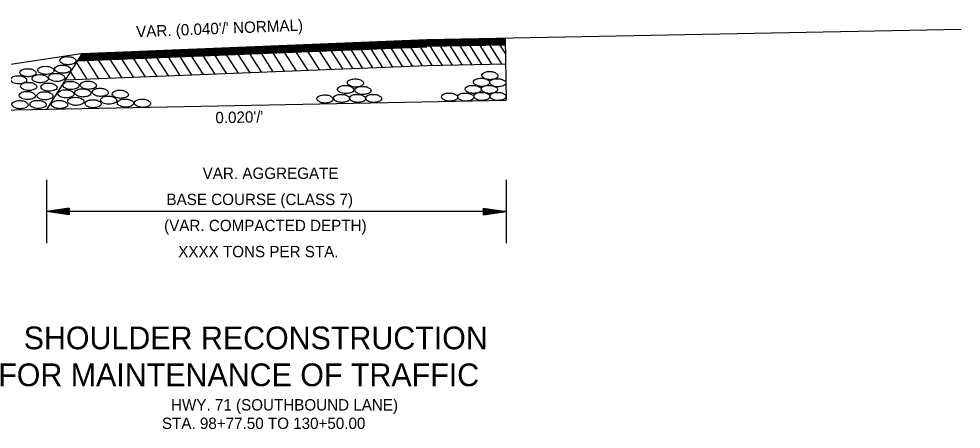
# Model space of a CAD drawing. Extents: x 635488 to 635865, y 290537 to 290973.
# Drawn here: x 635514.88 to 635564.67, y 290872.13 to 290893.8 of the extents above; entities that cross this region are included whole.
import ezdxf

# ---------------------------------------------------------------- set-up
doc = ezdxf.new("R2010")
doc.units = 0
doc.layers.add('Default', color=7, linetype='Continuous')

msp = doc.modelspace()

# ---------------------------------------------------------------- linework, layer by layer
at = {"layer": 'Default'}
for p, q in [((635564.67, 290893.24), (635536.434, 290892.685)), ((635536.434, 290892.3), (635517.962, 290891.558)), ((635536.434, 290892.333), (635517.979, 290891.586)), ((635536.434, 290892.37), (635518.005, 290891.63)), ((635536.434, 290892.412), (635518.029, 290891.67)), ((635536.434, 290892.45), (635518.061, 290891.714)), ((635536.434, 290892.488), (635518.083, 290891.748)), ((635536.434, 290892.524), (635518.111, 290891.792)), ((635536.434, 290892.566), (635518.133, 290891.832)), ((635536.434, 290892.608), (635518.164, 290891.878)), ((635536.434, 290892.641), (635518.183, 290891.907)), ((635536.434, 290892.685), (635518.211, 290891.952)), ((635540.583, 290892.724), (635536.434, 290892.641)), ((635540.584, 290892.691), (635536.434, 290892.608)), ((635540.584, 290892.65), (635536.434, 290892.566)), ((635540.585, 290892.609), (635536.434, 290892.524)), ((635540.586, 290892.572), (635536.434, 290892.488)), ((635540.586, 290892.533), (635536.434, 290892.45)), ((635540.587, 290892.495), (635536.434, 290892.412)), ((635540.587, 290892.452), (635536.434, 290892.37)), ((635540.588, 290892.415), (635536.434, 290892.333)), ((635537.267, 290891.333), (635536.632, 290892.337)), ((635537.793, 290891.343), (635537.158, 290892.347)), ((635538.318, 290891.353), (635537.684, 290892.357)), ((635538.844, 290891.364), (635538.21, 290892.368)), ((635539.37, 290891.374), (635538.735, 290892.378)), ((635539.896, 290891.385), (635539.261, 290892.388)), ((635540.421, 290891.395), (635539.787, 290892.399)), ((635540.595, 290891.962), (635540.313, 290892.409)), ((635540.583, 290892.735), (635540.634, 290889.503)), ((635518.177, 290891.946), (635487.759, 290887.399)), ((635518.211, 290891.952), (635516.341, 290889.006)), ((635524.648, 290890.851), (635524.03, 290891.801)), ((635525.257, 290890.875), (635524.644, 290891.826)), ((635525.873, 290890.899), (635525.261, 290891.854)), ((635526.485, 290890.923), (635525.87, 290891.879)), ((635527.106, 290890.947), (635526.487, 290891.901)), ((635527.714, 290890.972), (635527.101, 290891.924)), ((635528.329, 290890.996), (635527.715, 290891.951)), ((635528.945, 290891.02), (635528.331, 290891.974)), ((635529.555, 290891.044), (635528.94, 290892.001)), ((635530.174, 290891.069), (635529.557, 290892.026)), ((635530.788, 290891.094), (635530.168, 290892.049)), ((635531.403, 290891.117), (635530.786, 290892.072)), ((635532.019, 290891.142), (635531.4, 290892.097)), ((635532.541, 290891.162), (635531.935, 290892.122)), ((635533.065, 290891.183), (635532.462, 290892.141)), ((635533.595, 290891.204), (635532.988, 290892.164)), ((635534.123, 290891.225), (635533.513, 290892.181)), ((635534.65, 290891.246), (635534.041, 290892.207)), ((635535.175, 290891.267), (635534.567, 290892.227)), ((635535.699, 290891.287), (635535.091, 290892.249)), ((635536.215, 290891.312), (635535.612, 290892.267)), ((635536.741, 290891.322), (635536.131, 290892.288)), ((635536.454, 290891.317), (635517.329, 290890.562)), ((635518.499, 290890.608), (635517.926, 290891.502)), ((635519.117, 290890.632), (635518.504, 290891.582)), ((635519.732, 290890.657), (635519.119, 290891.606)), ((635520.345, 290890.681), (635519.733, 290891.63)), ((635520.957, 290890.706), (635520.346, 290891.655)), ((635521.574, 290890.729), (635520.964, 290891.678)), ((635522.186, 290890.754), (635521.578, 290891.705)), ((635522.805, 290890.778), (635522.192, 290891.73)), ((635523.414, 290890.802), (635522.805, 290891.751)), ((635524.032, 290890.826), (635523.419, 290891.778)), ((635540.604, 290891.398), (635536.454, 290891.317)), ((635517.887, 290890.584), (635517.611, 290891.011)), ((635540.634, 290889.491), (635495.751, 290888.594)), ((635516.341, 290885.291), (635516.341, 290881.955)), ((635540.634, 290885.291), (635540.634, 290881.955)), ((635517.541, 290883.803), (635516.341, 290883.623)), ((635540.634, 290883.623), (635516.341, 290883.623)), ((635517.541, 290883.443), (635516.341, 290883.623)), ((635517.541, 290883.773), (635516.541, 290883.623)), ((635517.541, 290883.473), (635516.541, 290883.623)), ((635517.541, 290883.742), (635516.748, 290883.623)), ((635517.541, 290883.504), (635516.748, 290883.623)), ((635517.541, 290883.712), (635516.948, 290883.623)), ((635517.541, 290883.534), (635516.948, 290883.623)), ((635517.541, 290883.681), (635517.151, 290883.623)), ((635517.541, 290883.564), (635517.151, 290883.623)), ((635517.541, 290883.651), (635517.351, 290883.623)), ((635517.541, 290883.595), (635517.351, 290883.623)), ((635517.541, 290883.803), (635517.541, 290883.443)), ((635539.434, 290883.803), (635540.634, 290883.623)), ((635539.434, 290883.443), (635539.434, 290883.803)), ((635539.434, 290883.773), (635540.434, 290883.623)), ((635539.434, 290883.742), (635540.227, 290883.623)), ((635539.434, 290883.712), (635540.027, 290883.623)), ((635539.434, 290883.682), (635539.824, 290883.623)), ((635539.434, 290883.651), (635539.624, 290883.623)), ((635539.434, 290883.443), (635540.634, 290883.623)), ((635539.434, 290883.565), (635539.824, 290883.623)), ((635539.434, 290883.504), (635540.227, 290883.623)), ((635539.434, 290883.473), (635540.434, 290883.623)), ((635539.434, 290883.534), (635540.027, 290883.623)), ((635539.434, 290883.595), (635539.624, 290883.623))]:
    msp.add_line(p, q, dxfattribs=at)
for points in [[(635517.485, 290891.798), (635517.335, 290891.797), (635517.153, 290891.733), (635517.061, 290891.649), (635517.048, 290891.596), (635517.097, 290891.504), (635517.151, 290891.462), (635517.246, 290891.412), (635517.398, 290891.381), (635517.471, 290891.37), (635517.585, 290891.382), (635517.706, 290891.402), (635517.8, 290891.441), (635517.89, 290891.51), (635517.906, 290891.571), (635517.877, 290891.652), (635517.809, 290891.708), (635517.743, 290891.75), (635517.645, 290891.781), (635517.583, 290891.797), (635517.485, 290891.798)], [(635517.209, 290891.351), (635517.058, 290891.349), (635516.877, 290891.287), (635516.787, 290891.2), (635516.771, 290891.15), (635516.819, 290891.056), (635516.872, 290891.014), (635516.971, 290890.969), (635517.119, 290890.93), (635517.195, 290890.924), (635517.307, 290890.932), (635517.43, 290890.954), (635517.525, 290890.992), (635517.613, 290891.063), (635517.628, 290891.123), (635517.602, 290891.203), (635517.533, 290891.261), (635517.469, 290891.304), (635517.366, 290891.335), (635517.304, 290891.349), (635517.209, 290891.351)], [(635515.373, 290891.162), (635515.222, 290891.161), (635515.038, 290891.1), (635514.949, 290891.013), (635514.935, 290890.964), (635514.984, 290890.868), (635515.037, 290890.827), (635515.136, 290890.782), (635515.284, 290890.745), (635515.358, 290890.738), (635515.471, 290890.746), (635515.595, 290890.767), (635515.688, 290890.805), (635515.78, 290890.877), (635515.791, 290890.935), (635515.764, 290891.016), (635515.697, 290891.072), (635515.632, 290891.116), (635515.532, 290891.148), (635515.468, 290891.161), (635515.373, 290891.162)], [(635516.017, 290890.849), (635515.869, 290890.848), (635515.685, 290890.785), (635515.598, 290890.698), (635515.582, 290890.648), (635515.629, 290890.555), (635515.683, 290890.514), (635515.782, 290890.466), (635515.928, 290890.428), (635516.006, 290890.424), (635516.115, 290890.43), (635516.24, 290890.45), (635516.335, 290890.491), (635516.424, 290890.561), (635516.438, 290890.62), (635516.41, 290890.703), (635516.341, 290890.759), (635516.28, 290890.802), (635516.177, 290890.832), (635516.113, 290890.848), (635516.017, 290890.849)], [(635516.319, 290891.289), (635516.168, 290891.287), (635515.987, 290891.225), (635515.895, 290891.137), (635515.884, 290891.089), (635515.93, 290890.994), (635515.983, 290890.954), (635516.081, 290890.905), (635516.23, 290890.868), (635516.305, 290890.862), (635516.417, 290890.873), (635516.54, 290890.893), (635516.637, 290890.93), (635516.724, 290891.003), (635516.74, 290891.061), (635516.713, 290891.142), (635516.643, 290891.198), (635516.579, 290891.24), (635516.477, 290891.273), (635516.416, 290891.287), (635516.319, 290891.289)], [(635516.888, 290890.913), (635516.74, 290890.911), (635516.556, 290890.852), (635516.469, 290890.765), (635516.453, 290890.715), (635516.5, 290890.62), (635516.554, 290890.58), (635516.653, 290890.533), (635516.799, 290890.495), (635516.877, 290890.489), (635516.988, 290890.497), (635517.111, 290890.517), (635517.206, 290890.558), (635517.296, 290890.629), (635517.309, 290890.686), (635517.282, 290890.768), (635517.214, 290890.823), (635517.151, 290890.866), (635517.048, 290890.901), (635516.986, 290890.911), (635516.888, 290890.913)], [(635539.783, 290891.011), (635539.63, 290891.01), (635539.448, 290890.946), (635539.359, 290890.863), (635539.347, 290890.809), (635539.393, 290890.717), (635539.445, 290890.678), (635539.545, 290890.626), (635539.691, 290890.592), (635539.767, 290890.584), (635539.878, 290890.595), (635540.004, 290890.616), (635540.099, 290890.653), (635540.187, 290890.726), (635540.202, 290890.784), (635540.176, 290890.866), (635540.106, 290890.919), (635540.042, 290890.961), (635539.94, 290890.996), (635539.877, 290891.01), (635539.783, 290891.011)], [(635514.876, 290890.788), (635514.727, 290890.787), (635514.546, 290890.724), (635514.455, 290890.637), (635514.44, 290890.589), (635514.488, 290890.495), (635514.543, 290890.452), (635514.641, 290890.407), (635514.789, 290890.371), (635514.864, 290890.363), (635514.973, 290890.372), (635515.099, 290890.393), (635515.193, 290890.43), (635515.284, 290890.5), (635515.297, 290890.561), (635515.269, 290890.643), (635515.2, 290890.698), (635515.138, 290890.742), (635515.037, 290890.771), (635514.971, 290890.787), (635514.876, 290890.788)], [(635515.412, 290890.441), (635515.261, 290890.439), (635515.079, 290890.375), (635514.987, 290890.29), (635514.973, 290890.24), (635515.023, 290890.146), (635515.076, 290890.104), (635515.172, 290890.056), (635515.323, 290890.019), (635515.397, 290890.014), (635515.51, 290890.022), (635515.632, 290890.043), (635515.727, 290890.082), (635515.816, 290890.153), (635515.83, 290890.215), (635515.803, 290890.293), (635515.735, 290890.349), (635515.669, 290890.393), (635515.571, 290890.425), (635515.509, 290890.439), (635515.412, 290890.441)], [(635516.486, 290890.403), (635516.332, 290890.399), (635516.149, 290890.338), (635516.06, 290890.251), (635516.05, 290890.201), (635516.096, 290890.106), (635516.148, 290890.065), (635516.246, 290890.017), (635516.394, 290889.981), (635516.47, 290889.975), (635516.581, 290889.984), (635516.703, 290890.006), (635516.799, 290890.043), (635516.888, 290890.114), (635516.904, 290890.174), (635516.877, 290890.257), (635516.808, 290890.31), (635516.743, 290890.354), (635516.643, 290890.386), (635516.579, 290890.399), (635516.486, 290890.403)], [(635517.648, 290890.491), (635517.495, 290890.49), (635517.313, 290890.426), (635517.224, 290890.343), (635517.212, 290890.289), (635517.258, 290890.197), (635517.31, 290890.158), (635517.41, 290890.106), (635517.556, 290890.072), (635517.632, 290890.064), (635517.743, 290890.075), (635517.869, 290890.096), (635517.964, 290890.133), (635518.052, 290890.206), (635518.067, 290890.264), (635518.041, 290890.346), (635517.971, 290890.399), (635517.907, 290890.441), (635517.805, 290890.476), (635517.742, 290890.49), (635517.648, 290890.491)], [(635518.561, 290890.502), (635518.408, 290890.501), (635518.226, 290890.437), (635518.137, 290890.354), (635518.125, 290890.3), (635518.171, 290890.208), (635518.223, 290890.169), (635518.323, 290890.117), (635518.469, 290890.083), (635518.545, 290890.075), (635518.656, 290890.086), (635518.782, 290890.107), (635518.877, 290890.144), (635518.965, 290890.217), (635518.98, 290890.275), (635518.954, 290890.357), (635518.884, 290890.41), (635518.82, 290890.452), (635518.718, 290890.487), (635518.655, 290890.501), (635518.561, 290890.502)], [(635532.676, 290890.621), (635532.523, 290890.62), (635532.341, 290890.556), (635532.252, 290890.473), (635532.24, 290890.419), (635532.286, 290890.327), (635532.338, 290890.288), (635532.438, 290890.236), (635532.584, 290890.202), (635532.66, 290890.194), (635532.771, 290890.205), (635532.897, 290890.226), (635532.992, 290890.263), (635533.08, 290890.336), (635533.095, 290890.394), (635533.069, 290890.476), (635532.999, 290890.529), (635532.935, 290890.571), (635532.833, 290890.606), (635532.77, 290890.62), (635532.676, 290890.621)], [(635539.334, 290890.657), (635539.181, 290890.656), (635538.999, 290890.592), (635538.91, 290890.509), (635538.898, 290890.455), (635538.944, 290890.363), (635538.996, 290890.324), (635539.096, 290890.272), (635539.242, 290890.238), (635539.318, 290890.23), (635539.429, 290890.241), (635539.555, 290890.262), (635539.65, 290890.299), (635539.738, 290890.372), (635539.753, 290890.43), (635539.727, 290890.512), (635539.657, 290890.565), (635539.593, 290890.607), (635539.491, 290890.642), (635539.428, 290890.656), (635539.334, 290890.657)], [(635540.196, 290890.634), (635540.043, 290890.633), (635539.861, 290890.569), (635539.772, 290890.486), (635539.76, 290890.432), (635539.806, 290890.34), (635539.858, 290890.301), (635539.958, 290890.249), (635540.104, 290890.215), (635540.18, 290890.207), (635540.291, 290890.218), (635540.417, 290890.239), (635540.512, 290890.276), (635540.6, 290890.349), (635540.615, 290890.407), (635540.589, 290890.489), (635540.519, 290890.542), (635540.455, 290890.584), (635540.353, 290890.619), (635540.29, 290890.633), (635540.196, 290890.634)], [(635515.341, 290889.959), (635515.189, 290889.958), (635515.007, 290889.894), (635514.915, 290889.808), (635514.901, 290889.758), (635514.951, 290889.665), (635515.004, 290889.623), (635515.101, 290889.574), (635515.252, 290889.537), (635515.325, 290889.532), (635515.439, 290889.54), (635515.56, 290889.562), (635515.655, 290889.601), (635515.744, 290889.671), (635515.758, 290889.733), (635515.732, 290889.811), (635515.663, 290889.867), (635515.598, 290889.911), (635515.5, 290889.944), (635515.437, 290889.958), (635515.341, 290889.959)], [(635516.269, 290889.947), (635516.115, 290889.942), (635515.933, 290889.881), (635515.844, 290889.794), (635515.833, 290889.744), (635515.88, 290889.649), (635515.931, 290889.609), (635516.029, 290889.56), (635516.177, 290889.525), (635516.254, 290889.518), (635516.364, 290889.528), (635516.486, 290889.55), (635516.583, 290889.587), (635516.671, 290889.657), (635516.687, 290889.718), (635516.66, 290889.8), (635516.592, 290889.853), (635516.526, 290889.897), (635516.427, 290889.93), (635516.363, 290889.942), (635516.269, 290889.947)], [(635517.379, 290890.046), (635517.226, 290890.045), (635517.044, 290889.981), (635516.955, 290889.898), (635516.943, 290889.844), (635516.989, 290889.752), (635517.041, 290889.713), (635517.141, 290889.661), (635517.287, 290889.627), (635517.363, 290889.619), (635517.474, 290889.63), (635517.6, 290889.651), (635517.695, 290889.688), (635517.783, 290889.761), (635517.798, 290889.819), (635517.772, 290889.901), (635517.702, 290889.954), (635517.638, 290889.996), (635517.536, 290890.031), (635517.473, 290890.045), (635517.379, 290890.046)], [(635518.27, 290890.097), (635518.117, 290890.096), (635517.935, 290890.032), (635517.846, 290889.949), (635517.834, 290889.895), (635517.88, 290889.803), (635517.932, 290889.764), (635518.032, 290889.712), (635518.178, 290889.678), (635518.254, 290889.67), (635518.365, 290889.681), (635518.491, 290889.702), (635518.586, 290889.739), (635518.674, 290889.812), (635518.689, 290889.87), (635518.663, 290889.952), (635518.593, 290890.005), (635518.529, 290890.047), (635518.427, 290890.082), (635518.364, 290890.096), (635518.27, 290890.097)], [(635519.193, 290890.128), (635519.04, 290890.127), (635518.858, 290890.063), (635518.769, 290889.98), (635518.757, 290889.926), (635518.803, 290889.834), (635518.855, 290889.795), (635518.955, 290889.743), (635519.101, 290889.709), (635519.177, 290889.701), (635519.288, 290889.712), (635519.414, 290889.733), (635519.509, 290889.77), (635519.597, 290889.843), (635519.612, 290889.901), (635519.586, 290889.983), (635519.516, 290890.036), (635519.452, 290890.078), (635519.35, 290890.113), (635519.287, 290890.127), (635519.193, 290890.128)], [(635520.251, 290890.025), (635520.098, 290890.024), (635519.916, 290889.96), (635519.827, 290889.877), (635519.815, 290889.823), (635519.861, 290889.731), (635519.913, 290889.692), (635520.013, 290889.64), (635520.159, 290889.606), (635520.235, 290889.598), (635520.346, 290889.609), (635520.472, 290889.63), (635520.567, 290889.667), (635520.655, 290889.74), (635520.67, 290889.798), (635520.644, 290889.88), (635520.574, 290889.933), (635520.51, 290889.975), (635520.408, 290890.01), (635520.345, 290890.024), (635520.251, 290890.025)], [(635531.947, 290889.808), (635531.794, 290889.807), (635531.612, 290889.743), (635531.523, 290889.66), (635531.511, 290889.606), (635531.557, 290889.514), (635531.609, 290889.475), (635531.709, 290889.423), (635531.855, 290889.389), (635531.931, 290889.381), (635532.042, 290889.392), (635532.168, 290889.413), (635532.263, 290889.45), (635532.351, 290889.523), (635532.366, 290889.581), (635532.34, 290889.663), (635532.27, 290889.716), (635532.206, 290889.758), (635532.104, 290889.793), (635532.041, 290889.807), (635531.947, 290889.808)], [(635532.156, 290890.274), (635532.003, 290890.273), (635531.821, 290890.209), (635531.732, 290890.126), (635531.72, 290890.072), (635531.766, 290889.98), (635531.818, 290889.941), (635531.918, 290889.889), (635532.064, 290889.855), (635532.14, 290889.847), (635532.251, 290889.858), (635532.377, 290889.879), (635532.472, 290889.916), (635532.56, 290889.989), (635532.575, 290890.047), (635532.549, 290890.129), (635532.479, 290890.182), (635532.415, 290890.224), (635532.313, 290890.259), (635532.25, 290890.273), (635532.156, 290890.274)], [(635532.791, 290889.808), (635532.638, 290889.807), (635532.456, 290889.743), (635532.367, 290889.66), (635532.355, 290889.606), (635532.401, 290889.514), (635532.453, 290889.475), (635532.553, 290889.423), (635532.699, 290889.389), (635532.775, 290889.381), (635532.886, 290889.392), (635533.012, 290889.413), (635533.107, 290889.45), (635533.195, 290889.523), (635533.21, 290889.581), (635533.184, 290889.663), (635533.114, 290889.716), (635533.05, 290889.758), (635532.948, 290889.793), (635532.885, 290889.807), (635532.791, 290889.808)], [(635533.072, 290890.23), (635532.919, 290890.229), (635532.737, 290890.165), (635532.648, 290890.082), (635532.636, 290890.028), (635532.682, 290889.936), (635532.734, 290889.897), (635532.834, 290889.845), (635532.98, 290889.811), (635533.056, 290889.803), (635533.167, 290889.814), (635533.293, 290889.835), (635533.388, 290889.872), (635533.476, 290889.945), (635533.491, 290890.003), (635533.465, 290890.085), (635533.395, 290890.138), (635533.331, 290890.18), (635533.229, 290890.215), (635533.166, 290890.229), (635533.072, 290890.23)], [(635533.634, 290889.808), (635533.481, 290889.807), (635533.299, 290889.743), (635533.21, 290889.66), (635533.198, 290889.606), (635533.244, 290889.514), (635533.296, 290889.475), (635533.396, 290889.423), (635533.542, 290889.389), (635533.618, 290889.381), (635533.729, 290889.392), (635533.855, 290889.413), (635533.95, 290889.45), (635534.038, 290889.523), (635534.053, 290889.581), (635534.027, 290889.663), (635533.957, 290889.716), (635533.893, 290889.758), (635533.791, 290889.793), (635533.728, 290889.807), (635533.634, 290889.808)], [(635537.655, 290889.877), (635537.502, 290889.876), (635537.32, 290889.812), (635537.231, 290889.729), (635537.219, 290889.675), (635537.265, 290889.583), (635537.317, 290889.544), (635537.417, 290889.492), (635537.563, 290889.458), (635537.639, 290889.45), (635537.75, 290889.461), (635537.876, 290889.482), (635537.971, 290889.519), (635538.059, 290889.592), (635538.074, 290889.65), (635538.048, 290889.732), (635537.978, 290889.785), (635537.914, 290889.827), (635537.812, 290889.862), (635537.749, 290889.876), (635537.655, 290889.877)], [(635538.507, 290889.877), (635538.354, 290889.876), (635538.172, 290889.812), (635538.083, 290889.729), (635538.071, 290889.675), (635538.117, 290889.583), (635538.169, 290889.544), (635538.269, 290889.492), (635538.415, 290889.458), (635538.491, 290889.45), (635538.602, 290889.461), (635538.728, 290889.482), (635538.823, 290889.519), (635538.911, 290889.592), (635538.926, 290889.65), (635538.9, 290889.732), (635538.83, 290889.785), (635538.766, 290889.827), (635538.664, 290889.862), (635538.601, 290889.876), (635538.507, 290889.877)], [(635538.902, 290890.283), (635538.749, 290890.282), (635538.567, 290890.218), (635538.478, 290890.135), (635538.466, 290890.081), (635538.512, 290889.989), (635538.564, 290889.95), (635538.664, 290889.898), (635538.81, 290889.864), (635538.886, 290889.856), (635538.997, 290889.867), (635539.123, 290889.888), (635539.218, 290889.925), (635539.306, 290889.998), (635539.321, 290890.056), (635539.295, 290890.138), (635539.225, 290890.191), (635539.161, 290890.233), (635539.059, 290890.268), (635538.996, 290890.282), (635538.902, 290890.283)], [(635539.358, 290889.913), (635539.205, 290889.912), (635539.023, 290889.848), (635538.934, 290889.765), (635538.922, 290889.711), (635538.968, 290889.619), (635539.02, 290889.58), (635539.12, 290889.528), (635539.266, 290889.494), (635539.342, 290889.486), (635539.453, 290889.497), (635539.579, 290889.518), (635539.674, 290889.555), (635539.762, 290889.628), (635539.777, 290889.686), (635539.751, 290889.768), (635539.681, 290889.821), (635539.617, 290889.863), (635539.515, 290889.898), (635539.452, 290889.912), (635539.358, 290889.913)], [(635539.756, 290890.283), (635539.603, 290890.282), (635539.421, 290890.218), (635539.332, 290890.135), (635539.32, 290890.081), (635539.366, 290889.989), (635539.418, 290889.95), (635539.518, 290889.898), (635539.664, 290889.864), (635539.74, 290889.856), (635539.851, 290889.867), (635539.977, 290889.888), (635540.072, 290889.925), (635540.16, 290889.998), (635540.175, 290890.056), (635540.149, 290890.138), (635540.079, 290890.191), (635540.015, 290890.233), (635539.913, 290890.268), (635539.85, 290890.282), (635539.756, 290890.283)], [(635540.207, 290889.913), (635540.054, 290889.912), (635539.872, 290889.848), (635539.783, 290889.765), (635539.771, 290889.711), (635539.817, 290889.619), (635539.869, 290889.58), (635539.969, 290889.528), (635540.115, 290889.494), (635540.191, 290889.486), (635540.302, 290889.497), (635540.428, 290889.518), (635540.523, 290889.555), (635540.611, 290889.628), (635540.626, 290889.686), (635540.6, 290889.768), (635540.53, 290889.821), (635540.466, 290889.863), (635540.364, 290889.898), (635540.301, 290889.912), (635540.207, 290889.913)], [(635514.956, 290889.478), (635514.804, 290889.476), (635514.622, 290889.412), (635514.53, 290889.327), (635514.516, 290889.277), (635514.566, 290889.183), (635514.619, 290889.141), (635514.716, 290889.093), (635514.867, 290889.056), (635514.94, 290889.051), (635515.054, 290889.059), (635515.175, 290889.08), (635515.27, 290889.119), (635515.359, 290889.19), (635515.373, 290889.252), (635515.347, 290889.33), (635515.278, 290889.386), (635515.213, 290889.43), (635515.115, 290889.462), (635515.052, 290889.476), (635514.956, 290889.478)], [(635515.909, 290889.49), (635515.755, 290889.486), (635515.573, 290889.425), (635515.484, 290889.338), (635515.473, 290889.288), (635515.52, 290889.193), (635515.571, 290889.152), (635515.669, 290889.104), (635515.817, 290889.068), (635515.894, 290889.062), (635516.004, 290889.071), (635516.126, 290889.093), (635516.223, 290889.13), (635516.311, 290889.2), (635516.327, 290889.261), (635516.3, 290889.344), (635516.232, 290889.397), (635516.166, 290889.44), (635516.067, 290889.473), (635516.003, 290889.486), (635515.909, 290889.49)], [(635517.04, 290889.479), (635516.887, 290889.478), (635516.705, 290889.414), (635516.616, 290889.331), (635516.604, 290889.277), (635516.65, 290889.185), (635516.702, 290889.146), (635516.802, 290889.094), (635516.948, 290889.06), (635517.024, 290889.052), (635517.135, 290889.063), (635517.261, 290889.084), (635517.356, 290889.121), (635517.444, 290889.194), (635517.459, 290889.252), (635517.433, 290889.334), (635517.363, 290889.387), (635517.299, 290889.429), (635517.197, 290889.464), (635517.134, 290889.478), (635517.04, 290889.479)], [(635517.899, 290889.651), (635517.746, 290889.65), (635517.564, 290889.586), (635517.475, 290889.503), (635517.463, 290889.449), (635517.509, 290889.357), (635517.561, 290889.318), (635517.661, 290889.266), (635517.807, 290889.232), (635517.883, 290889.224), (635517.994, 290889.235), (635518.12, 290889.256), (635518.215, 290889.293), (635518.303, 290889.366), (635518.318, 290889.424), (635518.292, 290889.506), (635518.222, 290889.559), (635518.158, 290889.601), (635518.056, 290889.636), (635517.993, 290889.65), (635517.899, 290889.651)], [(635518.821, 290889.526), (635518.668, 290889.525), (635518.486, 290889.461), (635518.397, 290889.378), (635518.385, 290889.324), (635518.431, 290889.232), (635518.483, 290889.193), (635518.583, 290889.141), (635518.729, 290889.107), (635518.805, 290889.099), (635518.916, 290889.11), (635519.042, 290889.131), (635519.137, 290889.168), (635519.225, 290889.241), (635519.24, 290889.299), (635519.214, 290889.381), (635519.144, 290889.434), (635519.08, 290889.476), (635518.978, 290889.511), (635518.915, 290889.525), (635518.821, 290889.526)], [(635519.634, 290889.714), (635519.481, 290889.713), (635519.299, 290889.649), (635519.21, 290889.566), (635519.198, 290889.512), (635519.244, 290889.42), (635519.296, 290889.381), (635519.396, 290889.329), (635519.542, 290889.295), (635519.618, 290889.287), (635519.729, 290889.298), (635519.855, 290889.319), (635519.95, 290889.356), (635520.038, 290889.429), (635520.053, 290889.487), (635520.027, 290889.569), (635519.957, 290889.622), (635519.893, 290889.664), (635519.791, 290889.699), (635519.728, 290889.713), (635519.634, 290889.714)], [(635520.525, 290889.558), (635520.372, 290889.557), (635520.19, 290889.493), (635520.101, 290889.41), (635520.089, 290889.356), (635520.135, 290889.264), (635520.187, 290889.225), (635520.287, 290889.173), (635520.433, 290889.139), (635520.509, 290889.131), (635520.62, 290889.142), (635520.746, 290889.163), (635520.841, 290889.2), (635520.929, 290889.273), (635520.944, 290889.331), (635520.918, 290889.413), (635520.848, 290889.466), (635520.784, 290889.508), (635520.682, 290889.543), (635520.619, 290889.557), (635520.525, 290889.558)], [(635521.423, 290889.548), (635521.27, 290889.547), (635521.088, 290889.483), (635520.999, 290889.4), (635520.987, 290889.346), (635521.033, 290889.254), (635521.085, 290889.215), (635521.185, 290889.163), (635521.331, 290889.129), (635521.407, 290889.121), (635521.518, 290889.132), (635521.644, 290889.153), (635521.739, 290889.19), (635521.827, 290889.263), (635521.842, 290889.321), (635521.816, 290889.403), (635521.746, 290889.456), (635521.682, 290889.498), (635521.58, 290889.533), (635521.517, 290889.547), (635521.423, 290889.548)], [(635531.067, 290889.776), (635530.914, 290889.775), (635530.732, 290889.711), (635530.643, 290889.628), (635530.631, 290889.574), (635530.677, 290889.482), (635530.729, 290889.443), (635530.829, 290889.391), (635530.975, 290889.357), (635531.051, 290889.349), (635531.162, 290889.36), (635531.288, 290889.381), (635531.383, 290889.418), (635531.471, 290889.491), (635531.486, 290889.549), (635531.46, 290889.631), (635531.39, 290889.684), (635531.326, 290889.726), (635531.224, 290889.761), (635531.161, 290889.775), (635531.067, 290889.776)]]:
    msp.add_spline(points, degree=3, dxfattribs=at)

# ---------------------------------------------------------------- texts
for s, rotation, p in [("VAR. (0.040'/' NORMAL)", 2.2923, (635521.094, 290892.821)), ("0.020'/'", 1.1457, (635525.273, 290888.28))]:
    msp.add_text(s, height=0.6, rotation=rotation, dxfattribs=at).set_placement(p)
for s, height, p in [('VAR. AGGREGATE', 0.6, (635524.596, 290885.342)), ('BASE COURSE (CLASS 7)', 0.6, (635522.685, 290883.963)), ('(VAR. COMPACTED DEPTH)', 0.6, (635522.56, 290882.584)), ('XXXX TONS PER STA.', 0.6, (635523.304, 290881.205)), ('SHOULDER RECONSTRUCTION', 1.2, (635515.142, 290876.346)), ('FOR MAINTENANCE OF TRAFFIC', 1.2, (635513.796, 290874.396)), ('HWY. 71 (SOUTHBOUND LANE)', 0.6, (635522.926, 290873.11)), ('STA. 98+77.50 TO 130+50.00', 0.6, (635522.444, 290872.135))]:
    msp.add_text(s, height=height, dxfattribs=at).set_placement(p)

doc.saveas('drawing.dxf')
